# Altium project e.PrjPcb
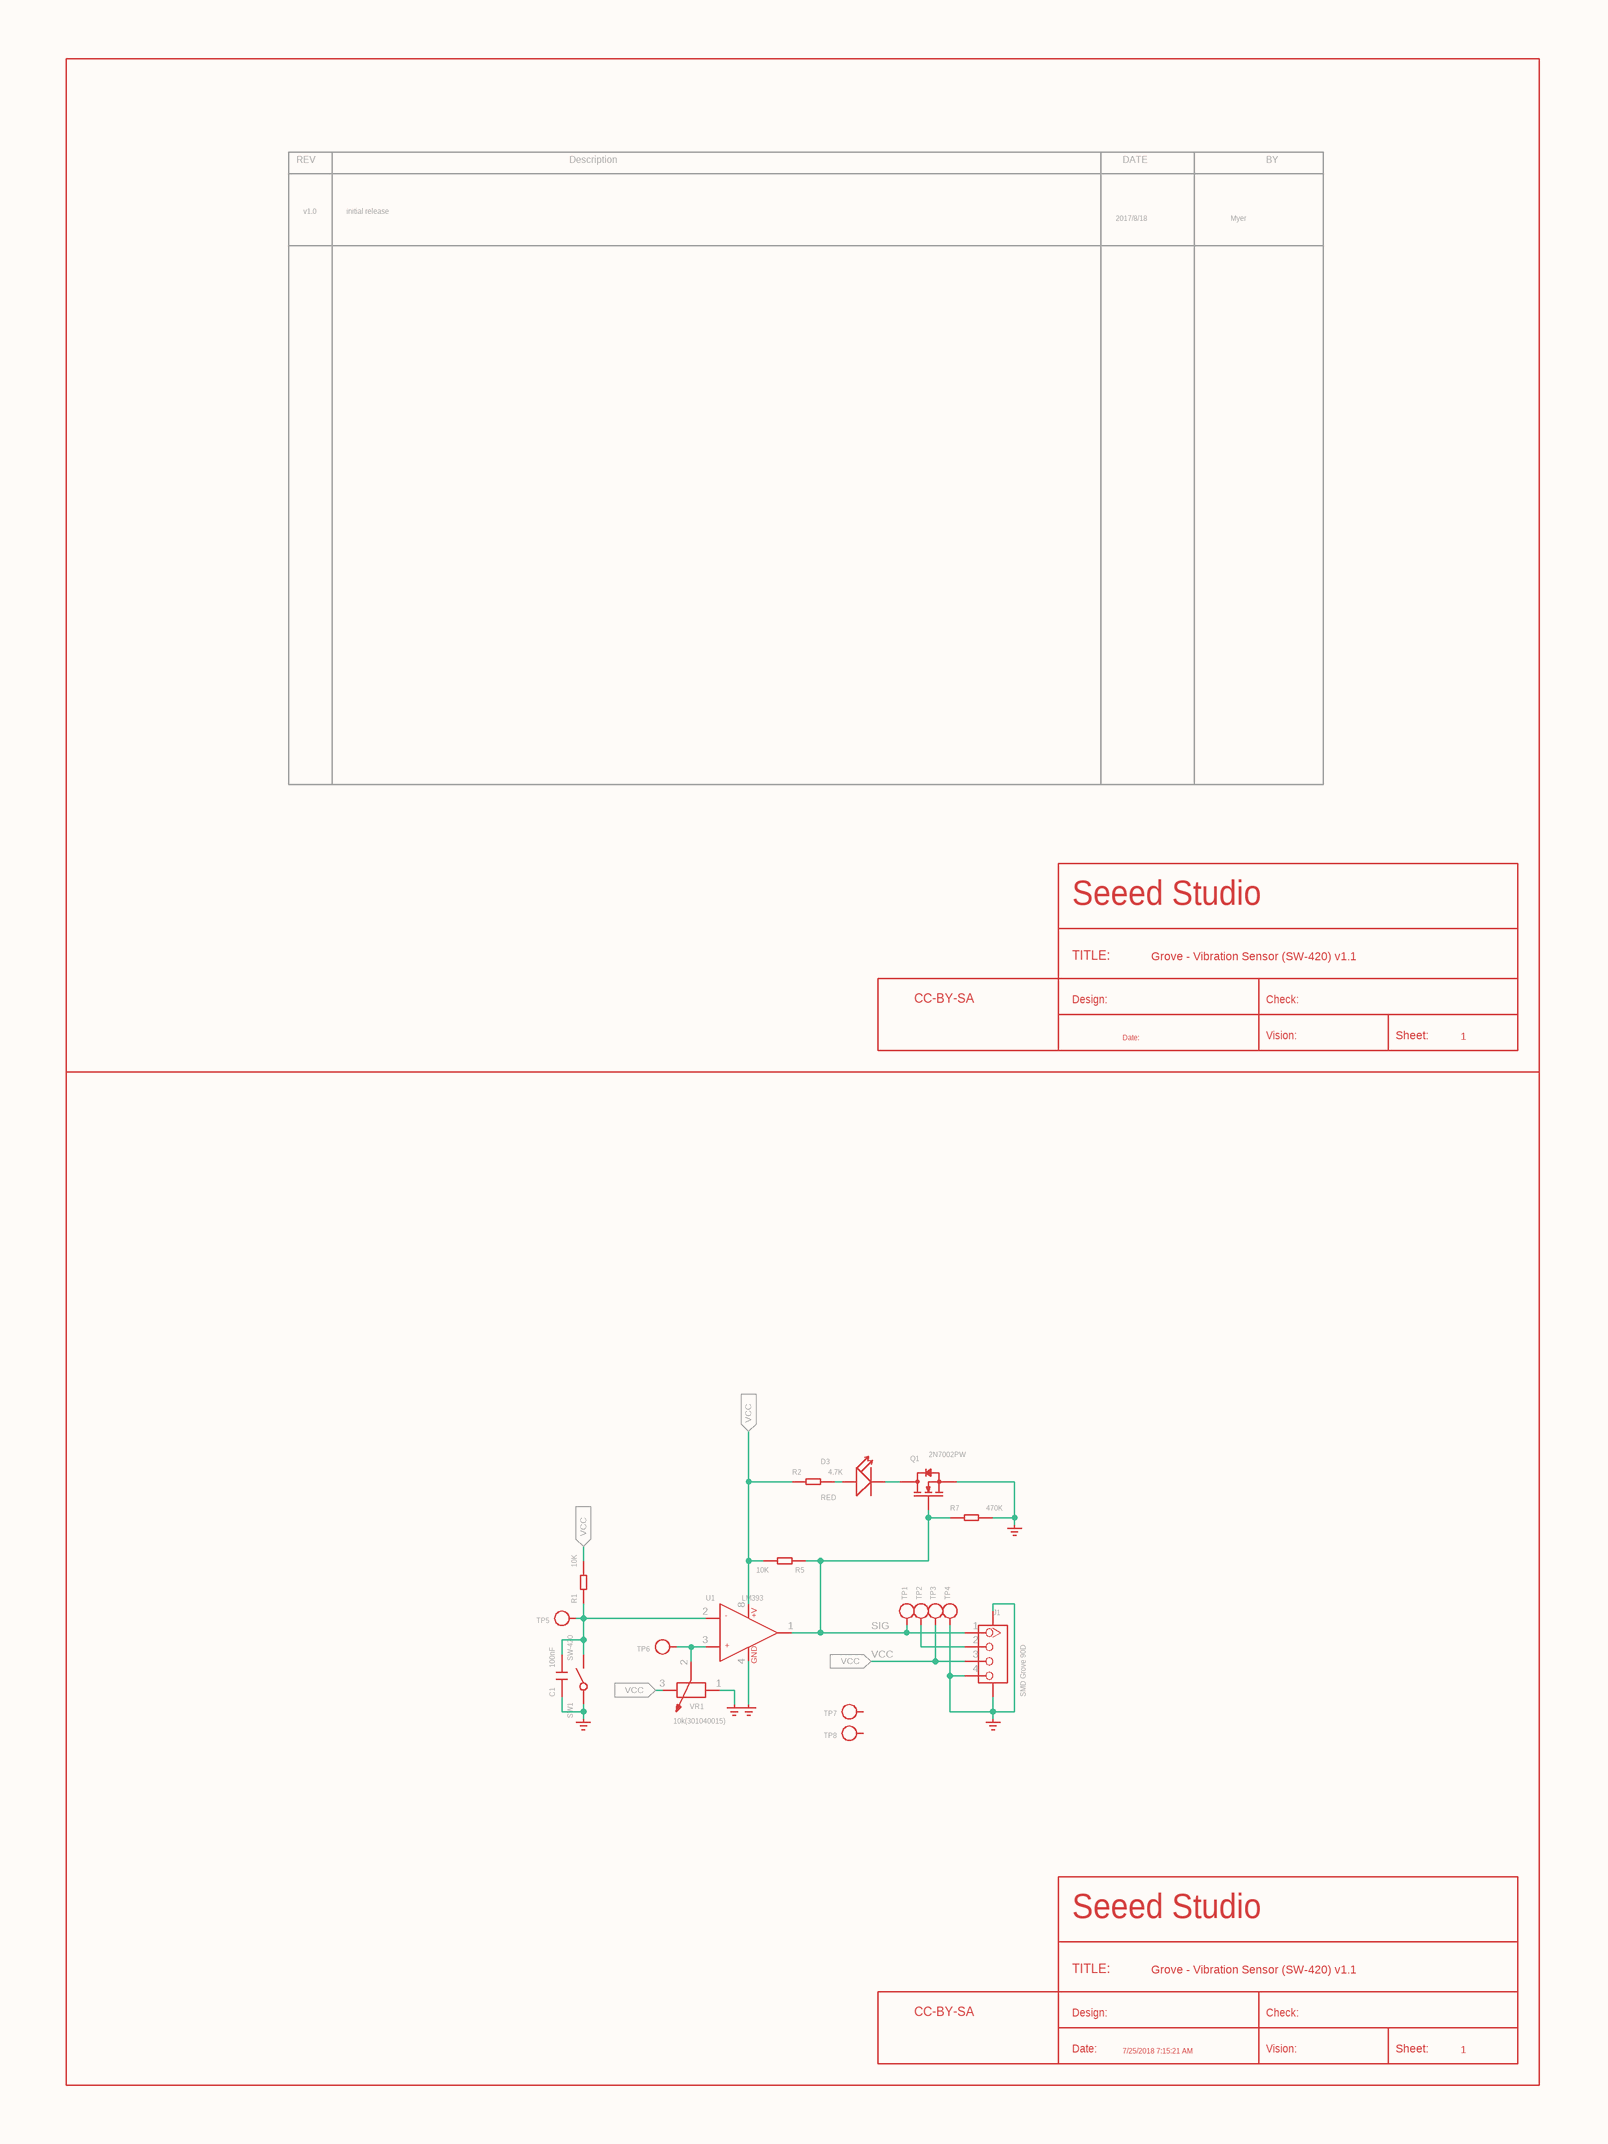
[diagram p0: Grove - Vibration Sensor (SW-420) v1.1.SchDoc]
1 sheet, 26 parts. Net scope: flat (ports and power ports of the same name join across sheets).
Board file: Grove - Vibration Sensor (SW-420) v1.1.PcbDoc

## Sheet Grove - Vibration Sensor (SW-420) v1.1.SchDoc: Grove - Vibration Sensor (SW-420) v1.1
size custom portrait; Date: 7/25/2018 7:15:21 AM; SheetNumber: 1; Origin: Eagle; GateName_1: G$1; SymbolName_1: SEEEDSTUDIO-OPEN-SCH-FRAME; LibraryName: moudle-new; DeviceSetName: SEEEDSTUDIO-OPEN-SCH-FRAME; Sheet: Sheet:; SeeedStudio: Seeed Studio; Design: Design:; Check: Check:; Vision: Vision:; CC-BY-SA: CC-BY-SA

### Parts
C1  100nF  [C0603]
D3  RED  [LED-0603]
FR2  DRAWING_NAME: Grove - Vibration Sensor (SW-420) v1.1  SHEET: 1  Sheet: Sheet:  SeeedStudio: Seeed Studio  TITLE: TITLE:  Design: Design:  Check: Check:  Vision: Vision:  Date: Date:  [SEEEDSTUDIO-PCB-FRAME]  (hidden comment: SEEEDSTUDIO-OPEN-SCH-FRAME)
J1  SMD Grove 90D  [HW4-SMD-2.0-90D]
Q1  2N7002PW  [SOT-23]
R1  10K  [R0603]
R2  4.7K  [R0603]
R5  10K  [R0603]
R7  470K  [R0603]
SW1  SW-420  [SW2-10.0-5X10MM]
TP1  TEST-POINT'4545'  [TP-D45MIL]  (value not drawn)
TP2  TEST-POINT'4545'  [TP-D45MIL]  (value not drawn)
TP3  TEST-POINT'4545'  [TP-D45MIL]  (value not drawn)
TP4  TEST-POINT'4545'  [TP-D45MIL]  (value not drawn)
TP5  TEST-POINT'4545'  [TP-D45MIL]  (value not drawn)
TP6  TEST-POINT'4545'  [TP-D45MIL]  (value not drawn)
TP7  TEST-POINT'4545'  [TP-D45MIL]  (value not drawn)
TP8  TEST-POINT'4545'  [TP-D45MIL]  (value not drawn)
U1  LM393  [SOIC8-1.27-5X4MM]
U$1  GND_POWER  (value not drawn)
U$2  GND_POWER  (value not drawn)
U$10  SEEDSTUDIO-SCH-MODLIST  (value not drawn)
U$11  GND_POWER  (value not drawn)
U$12  GND_POWER  (value not drawn)
U$13  GND_POWER  (value not drawn)
VR1  10k(301040015)  [ADJR3-SMD-4.6X3.7MM]

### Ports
VCC (in)

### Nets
SIG: J1.1 Q1.1(G) R5.1 R7.1 TP1.T U1.1(OUT1)
VCC: J1.3 R1.2 R2.1 R5.2 TP3.T U1.8(+V) VR1.3 ; port VCC
NetC1_1: C1.1 SW1.1 U$2.?1(GND)
NetC1_2: C1.2 R1.1 SW1.2 TP5.T U1.2(-IN1)
NetD3_+: D3.+ R2.2
NetD3_-: D3.- Q1.3(D)
NetJ1_2: J1.2 TP2.T
NetJ1_4: J1.4 J1.SS1 J1.SS2 TP4.T U$1.?1(GND)
NetQ1_2: Q1.2(S) R7.2 U$13.?1(GND)
NetTP6_T: TP6.T U1.3(+IN1) VR1.2
NetU1_4: U1.4(GND) U$12.?1(GND)
NetU$11_?1: U$11.?1(GND) VR1.1

Not connected (* = marked no-connect by the designer): TP7 T; TP8 T

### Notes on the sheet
- v1.0
- initial release
- 2017/8/18
- Myer
- Seeed Studio
- CC-BY-SA
- TITLE:
- Design:
- Grove - Vibration Sensor (SW-420) v1.1
- Check:
- Date:
- 7/25/2018 7:15:21 AM
- Vision:
- Sheet:
- 1

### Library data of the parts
C1 = C*-0603: Ceramic Capacitors; GateName_1: C; DeviceName: -0603; DeviceSetName: C*
D3 = LED'0603': GateName_1: LED; DeviceName: '0603'
FR2 = SEEEDSTUDIO-OPEN-SCH-FRAME: GateName_1: G$1
J1 = GROVE-CONNECTOR-SMD'90D': 4P-SMD-2.0:320110030;4P-SMD-2.0-90D:320110032; GateName_1: G$1; DeviceName: '90D'
Q1 = MOSFET-N'SOT23': GateName_1: MOS; SymbolName_1: N-MOS
R1 R2 R5 R7 = R*-0603: GateName_1: R; DeviceName: -0603; DeviceSetName: R*
SW1 = SWITCH-2P-SW-420: GateName_1: G$1
TP1-TP8 = TEST-POINT'4545': PARTNO: DNP; GateName_1: TP; DeviceName: '4545'
U1 = AMPLIFIER-LMV358'D': SOIC-8:310020002;MSOP-8:310020007; GateName_1: A; SymbolName_1: OPAMP_2; DeviceName: 'D'
U$1 U$2 U$11-U$13 = GND_POWER: GateName_1: G$1
U$10 = SEEDSTUDIO-SCH-MODLIST: GateName_1: G$1
VR1 = RES-ADJ'RTRIM3214W': Potentiometer; GateName_1: RP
